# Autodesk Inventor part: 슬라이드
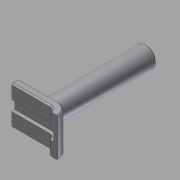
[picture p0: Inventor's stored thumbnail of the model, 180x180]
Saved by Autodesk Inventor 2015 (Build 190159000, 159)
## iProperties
Created: 2015-10
Part Number: 슬라이드
Document SubType Name: Modeling
Designer: mdu
Density: 7.86 g/cm^3
Material: 강철, 연강
Mass: 21.364 g
Surface Area: 19.6411 cm^2
Volume: 2.71807 cm^3
Appearance: 기본값
Author: mdu
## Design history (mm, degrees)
sketch "스케치1"
  geometry: L1 (10.279, 23.212)-(25.279, 23.212); L2 (10.279, 19.212)-(25.279, 19.212); L3 (25.279, 26.212)-(10.279, 26.212); L4 (10.279, 26.212)-(10.279, 16.212); L5 (10.279, 16.212)-(25.279, 16.212); C1 r 2 at (25.279, 21.212); A1 r 2 centre (25.279, 21.212) between (25.279, 23.212) and (25.279, 19.212) reference; A2 r 5 centre (25.279, 21.212) between (25.279, 26.212) and (25.279, 16.212); 1 further point
  constraints: 10 end point, 4 point on circle, 4 tangent, 3 parallel, 2 centre point, 2 coincident, 2 point on line, 1 horizontal, 1 perpendicular
  dimensions: "d0" = 4 diameter of C1; "d1" = 10 diameter of A2; "d4" = 15 distance from line of A2.centre L4
extrude "돌출1" new body sketch "스케치1" stored distance "d2" = 15; taper "d3" = 0 deg
sketch "스케치2"
  geometry: L1 (10.279, 26.212)-(10.279, 23.212) reference; L2 (10.279, 24.462)-(25.279, 24.462); L3 (27.779, 19.135)-(27.779, 6.212); L4 (27.779, 6.212)-(0.279, 6.212); L5 (0.279, 6.212)-(0.279, 24.462); L6 (10.279, 24.462)-(0.279, 24.462); A1 r 5 centre (25.279, 21.212) between (25.279, 16.212) and (25.279, 26.212) reference; A2 r 3.25 centre (25.279, 21.212) between (25.279, 24.462) and (27.779, 19.135); 1 further point
  constraints: 10 end point, 4 perpendicular, 2 point on circle, 1 centre point, 1 coincident, 1 parallel, 1 point on line, 1 tangent
  dimensions: "d5" = 6.5 diameter of A2; "d6" = 10 distance between parallel lines of L1 L5; "d7" = 10 distance from line of L4 A1.start; "d8" = 2.5 distance from line of L3 A1.centre
extrude "돌출2" cut sketch "스케치2" stored distance "d9" = 4; taper "d10" = 0 deg
sketch "스케치3"
  geometry: L1 (0, 15)-(0, 0) reference; C1 r 4 at (9.5, 7.5); 2 further points
  constraints: 1 centre point, 1 horizontal alignment, 1 midpoint
  dimensions: "d11" = 8 diameter of C1; "d12" = 9.5 distance from line of C1.centre L1
extrude "돌출3" join sketch "스케치3" distance "d13" = 40; taper "d14" = 0 deg
sketch "스케치4"
  geometry: C1 r 4 at (9.5, 7.5) reference; C2 r 4.65 at (9.5, 7.5); C3 r 6.75 at (9.5, 7.5); C4 r 5.5 at (9.5, 7.5); 1 further point
  constraints: 3 centre point, 3 coincident
  dimensions: "d15" = 9.3 diameter of C2; "d16" = 13.5 diameter of C3; "d19" = 11 diameter of C4
extrude "돌출4" cut sketch "스케치4" distance "d17" = 0.5; taper "d18" = 0 deg
sketch "스케치5"
  geometry: L1 (30.279, 21.212)-(7.279, 21.212); L2 (7.279, 21.212)-(7.279, 13.212); L3 (7.279, 13.212)-(31.947, 13.212); L4 (31.947, 13.212)-(31.947, 21.212); L5 (31.947, 21.212)-(30.279, 21.212); L6 (10.279, 16.212)-(10.279, 19.212) reference; A1 r 5 centre (25.279, 21.212) between (25.279, 16.212) and (25.279, 26.212) reference; 1 further point
  constraints: 10 end point, 2 perpendicular, 1 collinear, 1 horizontal, 1 parallel, 1 point on circle
  dimensions: "d20" = 3 distance between parallel lines of L2 L6; "d21" = 8 distance of L3.end L4.end
extrude "돌출5" cut sketch "스케치5" stored distance "d22" = 1; taper "d23" = 0 deg
chamfer "모따기1" distance "d24" = 0.5; stored, may be unused: second distance "d25" = 2, angle "d26" = 45 deg
hole "구멍1" diameter "d29" = 3.242; stored, may be unused: countersink angle "d33" = 90 deg, drill point angle "d35" = 118 deg; dims "d27" = 10, "d28" = 10, "d30" = 6, "d31" = 4, "d32" = 2, "d34" = 8
chamfer "모따기2" distance "d36" = 0.5; stored, may be unused: second distance "d37" = 2, angle "d38" = 45 deg
node "솔리드1"
node "참조1"
node "투영된 루프1"
